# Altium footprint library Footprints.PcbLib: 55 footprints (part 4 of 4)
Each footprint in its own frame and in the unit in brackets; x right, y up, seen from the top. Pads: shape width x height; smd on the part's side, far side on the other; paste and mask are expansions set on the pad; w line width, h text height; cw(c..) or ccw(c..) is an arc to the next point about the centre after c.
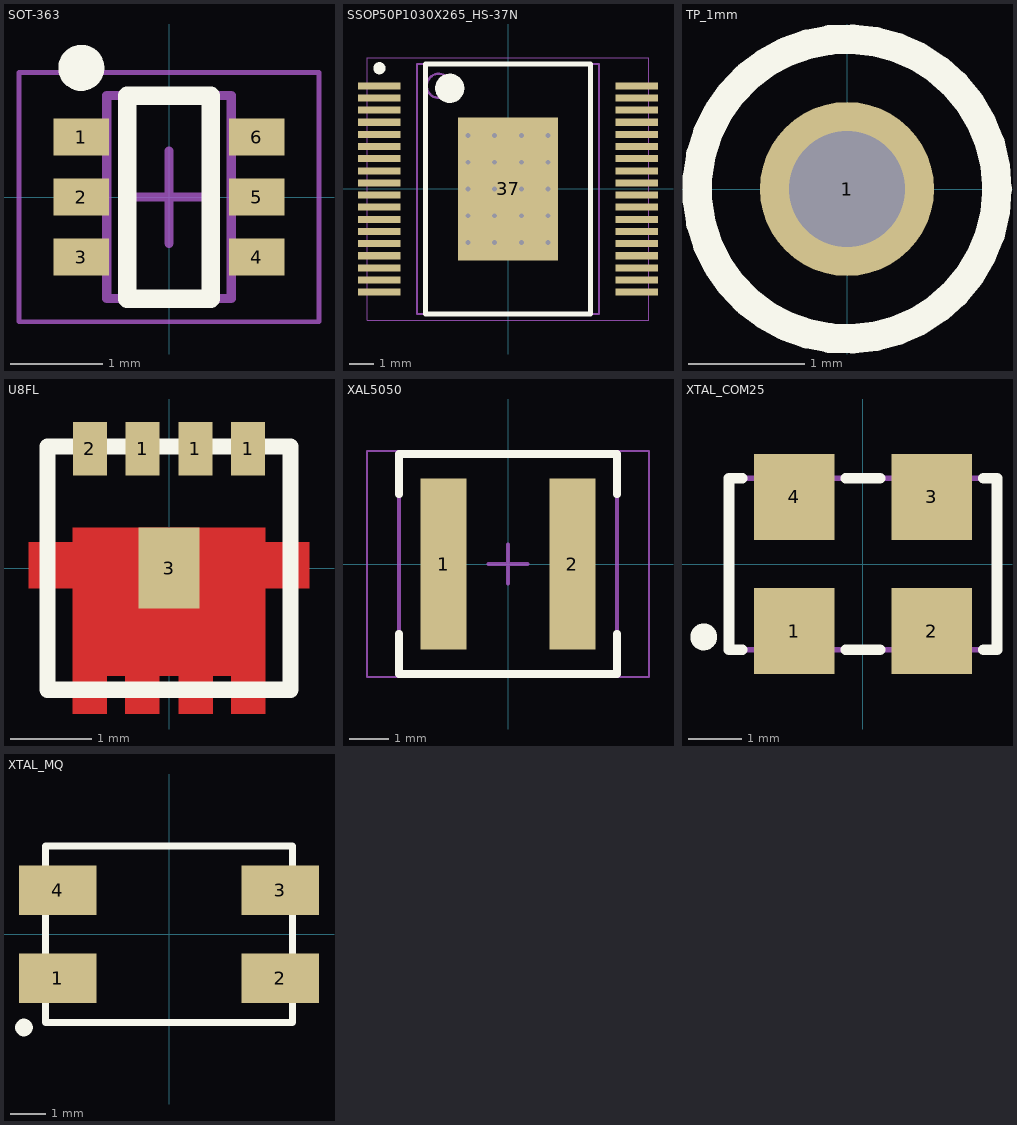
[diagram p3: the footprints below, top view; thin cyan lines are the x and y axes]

## SOT-363 [mm]
height 1.1
pads (6):
  rect 0.6x0.4 smd mask+0: 1(-0.95,0.65) 2(-0.95,0) 3(-0.95,-0.65) 4(0.95,-0.65) 5(0.95,0) 6(0.95,0.65)
Top Overlay:
  circle w0.25: c-0.95,1.4 r0.125
  lines w0.2: -0.45,-1.1 0.45,-1.1 0.45,1.1 -0.45,1.1 -0.45,-1.1
Top Solder:
  rectangle: 0.55,-0.95 1.35,0.95
  rectangle: -1.35,-0.95 -0.55,0.95
Mechanical 13:
  lines w0.1: -0.675,-1.1 -0.675,1.1 0.675,1.1 0.675,-1.1 -0.675,-1.1
Mechanical 15:
  lines w0.05: -1.625,-1.35 -1.625,1.35 1.625,1.35 1.625,-1.35 -1.625,-1.35
  lines w0.1: -0.5,0 0.5,0 ; 0,-0.5 0,0.5
3D body: height 1, standoff 0, extent -1.15,-1.05 1.15,1.05

## SSOP50P1030X265_HS-37N [mm] "SSOP, 36-Leads, Body 10.30x7.50mm, Pitch 0.50mm, Thermal Pad 5.90.2x4.10.2mm, IPC Medium Density"
height 2.65
pads (37):
  rect 1.76x0.29 smd: 1(-5.3,4.25) 2(-5.3,3.75) 3(-5.3,3.25) 4(-5.3,2.75) 5(-5.3,2.25) 6(-5.3,1.75) 7(-5.3,1.25) 8(-5.3,0.75) 9(-5.3,0.25) 10(-5.3,-0.25) 11(-5.3,-0.75) 12(-5.3,-1.25) 13(-5.3,-1.75) 14(-5.3,-2.25) 15(-5.3,-2.75) 16(-5.3,-3.25) 17(-5.3,-3.75) 18(-5.3,-4.25) 19(5.3,-4.25) 20(5.3,-3.75) 21(5.3,-3.25) 22(5.3,-2.75) 23(5.3,-2.25) 24(5.3,-1.75) 25(5.3,-1.25) 26(5.3,-0.75) 27(5.3,-0.25) 28(5.3,0.25) 29(5.3,0.75) 30(5.3,1.25) 31(5.3,1.75) 32(5.3,2.25) 33(5.3,2.75) 34(5.3,3.25) 35(5.3,3.75) 36(5.3,4.25)
  rect 4.1x5.9 smd: 37(0,0)
via -1.65,2.2 diameter 0.5 hole 0.2
via -0.55,2.2 diameter 0.5 hole 0.2
via 0.55,2.2 diameter 0.5 hole 0.2
via 1.65,2.2 diameter 0.5 hole 0.2
via -1.65,1.1 diameter 0.5 hole 0.2
via -0.55,1.1 diameter 0.5 hole 0.2
via 0.55,1.1 diameter 0.5 hole 0.2
via 1.65,1.1 diameter 0.5 hole 0.2
via -1.65,0 diameter 0.5 hole 0.2
via -0.55,0 diameter 0.5 hole 0.2
via 0.55,0 diameter 0.5 hole 0.2
via 1.65,0 diameter 0.5 hole 0.2
via -1.65,-1.1 diameter 0.5 hole 0.2
via -0.55,-1.1 diameter 0.5 hole 0.2
via 0.55,-1.1 diameter 0.5 hole 0.2
via 1.65,-1.1 diameter 0.5 hole 0.2
via -1.65,-2.2 diameter 0.5 hole 0.2
via -0.55,-2.2 diameter 0.5 hole 0.2
via 0.55,-2.2 diameter 0.5 hole 0.2
via 1.65,-2.2 diameter 0.5 hole 0.2
Top Overlay:
  circle w0.25: c-5.3,4.975 r0.125
  circle w0.6: c-2.4,4.15 r0.3
  lines w0.2: -3.4,-5.15 -3.4,5.15 3.4,5.15 3.4,-5.15 -3.4,-5.15
Mechanical 13:
  circle w0.1: c-2.85,4.25 r0.5
  lines w0.1: -3.75,-5.15 -3.75,5.15 3.75,5.15 3.75,-5.15 -3.75,-5.15
Mechanical 15:
  lines w0.05: -5.8,-5.4 -5.8,5.4 5.8,5.4 5.8,-5.4 -5.8,-5.4
  lines w0.1: -0.5,0 0.5,0 ; 0,-0.5 0,0.5
3D body: height 2.65, standoff 0.1, extent -3.75,-5.15 3.75,5.15

## TP_1mm [mm] "Testpoint DIA 1mm"
height 5
pads (1):
  round 1.5 hole 1: 1(0,0)
Top Overlay:
  circle w0.254: c0,0 r1.291
3D body: height 4.89, standoff -3.07, extent -1.27,-1.27 1.27,1.27

## U8FL [mm]
height 0.75
pads (5):
  rect 0.42x0.66 smd mask+0: 1(-0.325,1.47) 1(0.325,1.47) 1(0.975,1.47) 2(-0.975,1.47)
  rect 0.75x1 smd: 3(0,0)
Top Layer:
  region: -1.19,0.5 -1.19,0.32 -1.73,0.32 -1.73,-0.25 -1.19,-0.25 -1.19,-1.8 -0.77,-1.8 -0.77,-1.33 -0.54,-1.33 -0.54,-1.8 -0.12,-1.8 -0.12,-1.33 0.12,-1.33 0.12,-1.8 0.54,-1.8 0.54,-1.33 0.77,-1.33 0.77,-1.8 1.19,-1.8 1.19,-0.25 1.73,-0.25 1.73,0.32 1.19,0.32 1.19,0.5
Top Overlay:
  lines w0.2: -1.5,-1.5 -1.5,1.5 1.5,1.5 1.5,-1.5 -1.5,-1.5
Top Solder:
  rectangle: -1.3,1.05 1.3,1.9
3D body: height 0.8, standoff 0, extent -1.5,-1.52 1.5,1.5

## XAL5050 [mm] "Precision Wire Wound Inductor, 2-Leads, Coilcraft XAL5050"
height 5.1
pads (2):
  rect 1.18x4.4 smd: 1(-1.655,0) 2(1.655,0)
Top Overlay:
  lines w0.2: -2.8,-1.795 -2.8,-2.825 2.8,-2.825 2.8,-1.795 ; -2.8,1.795 -2.8,2.825 2.8,2.825 2.8,1.795
Mechanical 13:
  lines w0.1: -2.8,-2.85 -2.8,2.825 2.8,2.825 2.8,-2.85 -2.8,-2.85
Mechanical 15:
  lines w0.05: -3.625,-2.9 -3.625,2.9 3.625,2.9 3.625,-2.9 -3.625,-2.9
  lines w0.1: -0.5,0 0.5,0 ; 0,-0.5 0,0.5
3D body: height 5, standoff -0.1, extent -2.74,-2.84 2.74,2.84

## XTAL_COM25 [mm]
height 1
pads (4):
  rect 1.5x1.6 smd: 1(-1.28,-1.25) 2(1.28,-1.25) 3(1.28,1.25) 4(-1.28,1.25)
Top Overlay:
  circle w0.25: c-2.97,-1.36 r0.125
  lines w0.2: -2.25,-1.6 -2.5,-1.6 -2.5,1.6 -2.25,1.6 ; -0.32,-1.6 0.32,-1.6 ; -0.32,1.6 0.32,1.6 ; 2.25,-1.6 2.5,-1.6 2.5,1.6 2.25,1.6
Mechanical 13:
  lines w0.1: -2.51,-1.6 -2.51,1.6 2.5,1.6 2.5,-1.6 -2.51,-1.6
3D body: height 1, standoff 0.05, extent -2.51,-1.6 2.5,1.6

## XTAL_MQ [mm]
height 1.2
pads (4):
  rect 2.2x1.4 smd mask+0.102: 1(-3.15,-1.25)
  rect 2.2x1.4 smd: 2(3.15,-1.25) 3(3.15,1.25) 4(-3.15,1.25)
Top Overlay:
  circle w0.25: c-4.11,-2.64 r0.125
  lines w0.2: -3.5,-2.5 -3.5,2.5 3.5,2.5 3.5,-2.5 -3.5,-2.5
Mechanical 13:
  lines w0.1: -3.5,-2.5 3.5,-2.5 3.5,2.5 -3.5,2.5 -3.5,-2.5
3D body: height 1.2, standoff 0.05, extent -3.5,-2.5 3.5,2.5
